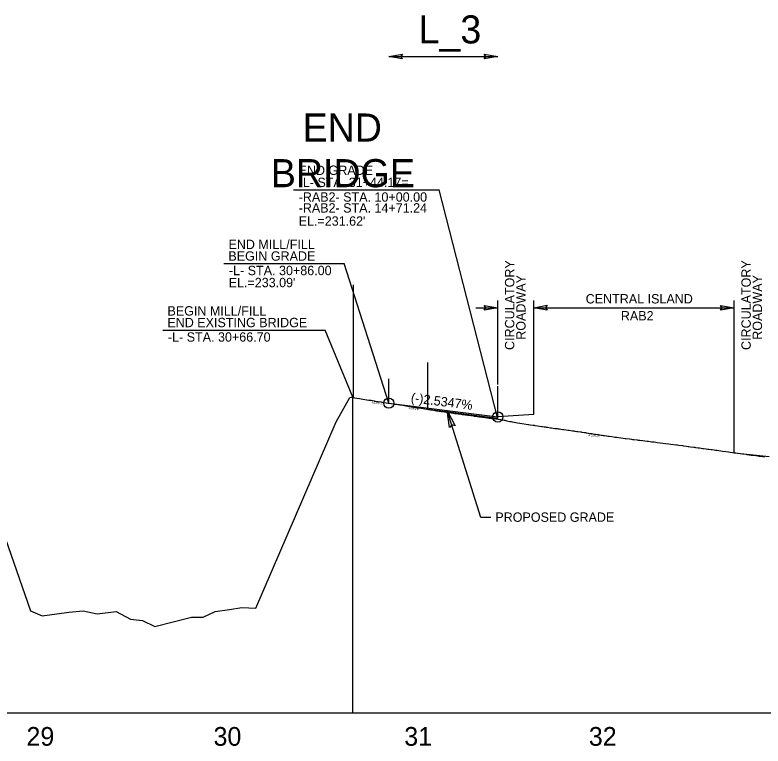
# Model space of a CAD drawing. Extents: x 2115752 to 2121174, y 562881 to 567245.
# Drawn here: x 2118582.7 to 2118982.1, y 566358.2 to 566748.6 of the extents above; entities that cross this region are included whole.
import ezdxf

# ---------------------------------------------------------------- set-up
doc = ezdxf.new("R2010")
doc.units = 0
for name, color, linetype in [('Exist Profile Cell', 7, 'Continuous'), ('Exist Vertical Profile Ground Line', 7, 'Continuous'), ('Exist Vertical Profile Horizontal Axis Label Major', 7, 'Continuous'), ('Prop Terminator CELL', 7, 'Continuous'), ('Prop Vertical Profile Grade', 7, 'Continuous'), ('Prop Vertical Profile Grade Label', 7, 'Continuous'), ('Prop VPI Label', 7, 'Continuous'), ('Scratch_Level_1', 7, 'Continuous')]:
    doc.layers.add(name, color=color, linetype=linetype)

msp = doc.modelspace()

# ---------------------------------------------------------------- linework, layer by layer
at = {"layer": 'Exist Profile Cell'}
msp.add_line((2116696.3, 566375.81), (2121174.42, 566375.81), dxfattribs=at)
at = {"layer": 'Exist Vertical Profile Ground Line'}
for points in [[(2118761.39, 566544.37), (2118762.34, 566544.55), (2118762.75, 566544.5), (2118764.05, 566544.17), (2118765.15, 566543.99), (2118766.63, 566543.74), (2118767.61, 566543.58), (2118768.49, 566543.43), (2118770.5, 566543.12), (2118771.71, 566542.95), (2118772.9, 566542.79), (2118774.42, 566542.52), (2118774.99, 566542.43), (2118778.28, 566541.93), (2118778.69, 566541.87), (2118782.01, 566541.32), (2118783.61, 566541.08), (2118784.88, 566540.88), (2118785.34, 566540.81), (2118785.92, 566540.71), (2118787.15, 566540.55), (2118788.1, 566540.4), (2118789.77, 566540.12), (2118791.34, 566539.84), (2118792.4, 566539.68), (2118793.67, 566539.48), (2118794.72, 566539.32), (2118797.51, 566538.86), (2118797.95, 566538.79), (2118799.53, 566538.59), (2118801.5, 566538.25), (2118804.55, 566537.8), (2118804.86, 566537.74), (2118805.24, 566537.67), (2118807.81, 566537.25), (2118808.42, 566537.16), (2118809.19, 566537.03), (2118810.21, 566536.89), (2118811.03, 566536.77), (2118813.01, 566536.47), (2118814.34, 566536.27), (2118816.88, 566535.92), (2118817.26, 566535.86), (2118817.59, 566535.82), (2118820.87, 566535.37), (2118821.37, 566535.29), (2118824.55, 566534.85), (2118826.14, 566534.63), (2118827.43, 566534.46), (2118827.94, 566534.4), (2118828.49, 566534.31), (2118828.83, 566534.27), (2118829.69, 566534.15), (2118830.69, 566534.01), (2118831.45, 566533.92), (2118832.36, 566533.79), (2118833.52, 566533.63), (2118833.98, 566533.57), (2118835.02, 566533.46), (2118835.86, 566533.34), (2118836.31, 566533.28), (2118837.22, 566533.16), (2118838.2, 566533.02), (2118840.55, 566532.71), (2118842.12, 566532.52), (2118842.89, 566532.38), (2118843.92, 566532.18), (2118844.22, 566532.12), (2118845.23, 566531.91), (2118846.93, 566531.56), (2118847.57, 566531.41), (2118848.11, 566531.29), (2118849.23, 566531.07), (2118850.1, 566530.92), (2118851.01, 566530.76), (2118852.26, 566530.54), (2118853.3, 566530.38), (2118854.6, 566530.18), (2118856.48, 566529.91), (2118856.94, 566529.85), (2118857.68, 566529.75), (2118859.29, 566529.54), (2118859.9, 566529.46), (2118860.26, 566529.41), (2118861.72, 566529.22), (2118862.75, 566529.04), (2118863.97, 566528.85), (2118864.34, 566528.79), (2118865.24, 566528.67), (2118865.94, 566528.57), (2118866.31, 566528.51), (2118867.07, 566528.4), (2118868.66, 566528.18), (2118869.12, 566528.12), (2118871, 566527.83), (2118872.17, 566527.66), (2118872.66, 566527.59), (2118873.34, 566527.5), (2118874.17, 566527.39), (2118875.28, 566527.22), (2118875.68, 566527.17)], [(2118558.09, 566524.65), (2118590.94, 566430.42), (2118597.22, 566427.62), (2118605.04, 566428.83), (2118611.5, 566429.7), (2118619.14, 566430.34), (2118626.58, 566428.81), (2118636.63, 566429.99), (2118644.39, 566425.91), (2118650.82, 566425.28), (2118657.41, 566421.93), (2118676.93, 566427), (2118683.13, 566427.04), (2118689.5, 566430.06), (2118697.24, 566431.16), (2118703.78, 566432.15), (2118711.34, 566431.83), (2118754.2, 566531.37), (2118761.39, 566544.37)], [(2118875.68, 566527.17), (2118876.91, 566527), (2118878.03, 566526.85), (2118878.45, 566526.79), (2118880.37, 566526.53), (2118881.15, 566526.42), (2118881.53, 566526.37), (2118882.71, 566526.2), (2118883.13, 566526.14), (2118884.57, 566525.95), (2118885.05, 566525.88), (2118885.42, 566525.83), (2118886.74, 566525.63), (2118887.4, 566525.53), (2118887.7, 566525.48), (2118889.74, 566525.16), (2118890.32, 566525.06), (2118890.76, 566525), (2118892.11, 566524.77), (2118894.12, 566524.47), (2118894.42, 566524.42), (2118895.69, 566524.22), (2118896.81, 566524.07), (2118897.5, 566523.96), (2118898.57, 566523.81), (2118899.37, 566523.69), (2118899.89, 566523.63), (2118901.45, 566523.4), (2118903.01, 566523.17), (2118903.79, 566523.07), (2118906.14, 566522.76), (2118907.34, 566522.6), (2118908.48, 566522.46), (2118908.93, 566522.4), (2118910.82, 566522.16), (2118911.94, 566522.01), (2118912.4, 566521.95), (2118913.16, 566521.85), (2118914.93, 566521.61), (2118915.51, 566521.53), (2118916.29, 566521.44), (2118917.89, 566521.25), (2118919.07, 566521.09), (2118920.17, 566520.98), (2118920.91, 566520.9), (2118922.75, 566520.71), (2118923.9, 566520.55), (2118924.81, 566520.44), (2118925.49, 566520.35), (2118927.13, 566520.16), (2118929.99, 566519.82), (2118931.77, 566519.59), (2118932.93, 566519.44), (2118934.37, 566519.26), (2118935.96, 566519.08), (2118936.41, 566519.01), (2118937.14, 566518.89), (2118939.06, 566518.65), (2118939.72, 566518.55), (2118941.04, 566518.34), (2118942.11, 566518.17), (2118942.56, 566518.1), (2118943.36, 566518.01), (2118945.11, 566517.78), (2118945.68, 566517.69), (2118946.12, 566517.62), (2118947.48, 566517.46), (2118948.15, 566517.37), (2118949.93, 566517.14), (2118950.32, 566517.08), (2118951.73, 566516.9), (2118952.64, 566516.79), (2118953.24, 566516.72), (2118954.35, 566516.55), (2118955.02, 566516.46), (2118956.02, 566516.34), (2118956.74, 566516.26), (2118957.43, 566516.16), (2118958.57, 566515.99), (2118959.6, 566515.85), (2118960.53, 566515.72), (2118962.16, 566515.48), (2118963.65, 566515.27), (2118964.48, 566515.15), (2118965.79, 566514.97), (2118966.75, 566514.82), (2118967.57, 566514.72), (2118968.88, 566514.53), (2118969.92, 566514.38), (2118971.2, 566514.2), (2118973.03, 566513.95), (2118973.52, 566513.88), (2118974.67, 566513.73), (2118975.84, 566513.58), (2118976.21, 566513.53), (2118976.51, 566513.49), (2118976.87, 566513.44), (2118978.25, 566513.26), (2118979.35, 566513.12), (2118980.04, 566513.05), (2118980.48, 566512.98)], [(2118980.48, 566512.98), (2118980.95, 566512.91), (2118981.81, 566512.81), (2118982.8, 566512.69)]]:
    msp.add_lwpolyline(points, dxfattribs=at)
at = {"layer": 'Prop Terminator CELL'}
for points in [[(2118833.27, 566593.49), (2118840.47, 566592.25), (2118833.23, 566590.97), (2118834.15, 566592.25)], [(2118866.89, 566591.01), (2118859.69, 566592.25), (2118866.93, 566593.53), (2118866.01, 566592.25)], [(2118959.45, 566593.49), (2118966.65, 566592.25), (2118959.41, 566590.97), (2118960.33, 566592.25)], [(2118814.74, 566528.27), (2118813.53, 566537.32), (2118817.76, 566529.16), (2118815.89, 566529.78)]]:
    msp.add_lwpolyline(points, close=True, dxfattribs=at)
at = {"layer": 'Prop Vertical Profile Grade'}
msp.add_line((2118782.3, 566541.28), (2118840.47, 566533.91), dxfattribs=at)
at = {"layer": 'Prop VPI Label'}
for p, q in [((2118731.43, 566655.12), (2118809.18, 566655.12)), ((2118840.47, 566532.91), (2118809.18, 566655.12)), ((2118694.25, 566615.8), (2118758.53, 566615.8)), ((2118782.3, 566541.28), (2118758.53, 566615.8)), ((2118840.47, 566551.17), (2118840.47, 566596.16)), ((2118859.69, 566535.14), (2118859.69, 566596.16)), ((2118966.65, 566514.53), (2118966.65, 566596.16)), ((2118828.68, 566592.25), (2118840.47, 566592.25)), ((2118859.69, 566592.25), (2118966.65, 566592.25)), ((2118661.68, 566580.3), (2118748.22, 566580.3)), ((2118763, 566544.46), (2118748.22, 566580.3)), ((2118859.69, 566535.14), (2118840.47, 566533.91)), ((2118985.32, 566512.53), (2118966.65, 566514.53))]:
    msp.add_line(p, q, dxfattribs=at)
msp.add_lwpolyline([(2118836.72, 566480.15), (2118831.42, 566480.15), (2118813.53, 566537.32)], dxfattribs=at)
for centre in [(2118782.3, 566541.28), (2118840.47, 566533.91)]:
    msp.add_circle(centre, 2.75, dxfattribs=at)
at = {"layer": 'Scratch_Level_1'}
for p, q in [((2118782.3, 566726.39), (2118840.47, 566726.39)), ((2118763.41, 566544.33), (2118763.41, 566604.44)), ((2118803.17, 566538), (2118803.17, 566562.93)), ((2118782.3, 566541.28), (2118782.3, 566554.29)), ((2118840.47, 566532.91), (2118840.47, 566550.41)), ((2118763, 566375.81), (2118763, 566544.46)), ((2118774.99, 566542.43), (2118778.28, 566541.93)), ((2118797.51, 566538.86), (2118794.72, 566539.32)), ((2118803.17, 566538), (2118840.4, 566533.29)), ((2118887.7, 566525.48), (2118899.89, 566523.63))]:
    msp.add_line(p, q, dxfattribs=at)
for points in [[(2118789.5, 566725.15), (2118782.3, 566726.39), (2118789.54, 566727.67), (2118788.62, 566726.39)], [(2118833.27, 566727.63), (2118840.47, 566726.39), (2118833.23, 566725.11), (2118834.15, 566726.39)]]:
    msp.add_lwpolyline(points, close=True, dxfattribs=at)

# ---------------------------------------------------------------- texts
at = {"layer": 'Exist Vertical Profile Horizontal Axis Label Major'}
for s, p in [('29', (2118588.81, 566358.31)), ('30', (2118688.69, 566358.31)), ('31', (2118790.53, 566358.31)), ('32', (2118889.08, 566358.31))]:
    msp.add_text(s, height=10, dxfattribs=at).set_placement(p)
at = {"layer": 'Prop Vertical Profile Grade Label'}
msp.add_text('(-)2.5347%', height=5, rotation=352.777, dxfattribs=at).set_placement((2118793.87, 566541.8))
at = {"layer": 'Prop VPI Label'}
for s, p in [('END GRADE', (2118734.11, 566663.17)), ('-L- STA. 31+44.17=', (2118734.15, 566656.7)), ('-RAB2- STA. 10+00.00', (2118734.15, 566648.87)), ('-RAB2- STA. 14+71.24', (2118734.15, 566643.05)), ("EL.=231.62'", (2118734.15, 566636.05)), ('END MILL/FILL', (2118696.68, 566623.56)), ('BEGIN GRADE', (2118696.63, 566617.35)), ('-L- STA. 30+86.00', (2118696.92, 566609.63)), ("EL.=233.09'", (2118696.78, 566603.2)), ('CENTRAL ISLAND', (2118887.4, 566594.52)), ('BEGIN MILL/FILL', (2118664.1, 566588.05)), ('RAB2', (2118906.19, 566585.46)), ('END EXISTING BRIDGE', (2118664.05, 566581.84)), ('-L- STA. 30+66.70', (2118664.34, 566574.12)), ('PROPOSED GRADE', (2118839.16, 566477.91))]:
    msp.add_text(s, height=5, dxfattribs=at).set_placement(p)
for s, p in [('CIRCULATORY', (2118849.3, 566569.67)), ('CIRCULATORY', (2118975.56, 566569.67)), ('ROADWAY', (2118855.3, 566575.14)), ('ROADWAY', (2118981.57, 566575.14))]:
    msp.add_text(s, height=5, rotation=90, dxfattribs=at).set_placement(p)
at = {"layer": 'Scratch_Level_1'}
for s, p in [('L_3', (2118798.18, 566733.37)), ('END', (2118736.25, 566680.97)), ('BRIDGE', (2118719.3, 566656.6))]:
    msp.add_text(s, height=15, dxfattribs=at).set_placement(p)
for s, rotation, p in [('-3.0269 %', 351.3938, (2118772.54, 566541.38)), ('-3.2698 %', 350.7149, (2118792.25, 566538.35)), ('-3.0396 %', 351.3582, (2118888.49, 566523.86))]:
    msp.add_text(s, height=1, rotation=rotation, dxfattribs=at).set_placement(p)

doc.saveas('drawing.dxf')
